(* Logix 5000 project; controller Hardy_1769_Sample_Program vendor 1 type 14 code 151 rev 30.11; software revision 30.02 *)

TASK MainTask (continuous, watchdog 500 ms) : Hardy_HI1769_Scale_0, Hardy_HI1769_Scale_1

MODULES
   Local : vendor 1 type 14 code 151 (Compact 0, rev 30.11)
      Counters : Embedded (Compact 3, rev 1.1, Output RPI 20 ms)
      Hardy_HI1769_2WS : vendor 258 type 100 code 5 (Compact 4, rev 3.1, Output RPI 2 ms)
      Discrete_IO : Embedded (Compact 1, rev 3.1, Output RPI 20 ms)
      Analog_IO : Embedded (Compact 2, rev 1.1, Output RPI 80 ms)
END_MODULES

TYPE HardyC2SerialNumber :   // C2 serial number, sensitivity, and capacity
STRUCT
   serialnumber : INT[8];
   sensitivity : DINT;
   capacity : DINT;
   unused0 : INT;
   unused1 : INT;
END_STRUCT
END_TYPE

TYPE HardyCmdResult :   // Results returned for commands without specific data associated with command.
STRUCT
   Cmd : INT;
   CmdStatus : INT;
END_STRUCT
END_TYPE

TYPE HardyFloatParam0 :   // parameter 0 values using float values.
STRUCT
   ChanActive : INT;
   Metric : INT;
   Waversaver : INT;
   NumAverages : INT;
   ZeroTrackEnable : INT;
   ROC_Time_Base : INT;
   AutoZeroTol : REAL;
   MotionTol : REAL;
   ZeroTol : REAL;
   unused1 : INT;
   unused2 : INT;
END_STRUCT
END_TYPE

TYPE HardyFloatParam1 :   // parameter 1 values with float variables.
STRUCT
   TareWeight : REAL;
   SpanWeight : REAL;
   CalLowWeight : REAL;
   ZeroCount : DINT;
   CalZeroCount : DINT;
   CalLowCount : DINT;
   CalHighCount : DINT;
END_STRUCT
END_TYPE

TYPE HardyFloatSysTest :   // With IT jbox, gives weight readings from individual load cells, internal ref weight and junction box ref weight with floats..
STRUCT
   Cmd : INT;
   NSensors : INT;
   CombinedGross : REAL;
   Gross1 : REAL;
   Gross2 : REAL;
   Gross3 : REAL;
   Gross4 : REAL;
   InternalWgt : REAL;
   JBOXWgt : REAL;
END_STRUCT
END_TYPE

TYPE HardyFloatWeight :   // default return from module when no command given.
STRUCT
   Channel_Status : INT;
   FirmwareRev : INT;
   Gross_Weight : REAL;
   Net_Weight : REAL;
   Metric : INT;
   CalType : INT;
   ADC_Counts : DINT;
   Rate_of_Change : REAL;
   Serial_Number : INT;
   Conv_Count : INT;
END_STRUCT
END_TYPE

TYPE HardyIntParam0 :   // parameter 0 values using integer values.
STRUCT
   ChanActive : INT;
   Metric : INT;
   Waversaver : INT;
   NumAverages : INT;
   ZeroTrackEnable : INT;
   ROC_Time_Base : INT;
   AutoZeroTol : DINT;
   MotionTol : DINT;
   ZeroTol : DINT;
   unused1 : INT;
   unused2 : INT;
END_STRUCT
END_TYPE

TYPE HardyIntParam1 :   // parameter 1 values with integer variables.
STRUCT
   TareWeight : DINT;
   SpanWeight : DINT;
   CalLowWeight : DINT;
   ZeroCount : DINT;
   CalZeroCount : DINT;
   CalLowCount : DINT;
   CalHighCount : DINT;
END_STRUCT
END_TYPE

TYPE HardyIntSysTest :   // With IT jbox, gives weight readings from individual load cells, internal ref weight and junction box ref weight with integer.
STRUCT
   Cmd : INT;
   NSensors : INT;
   CombinedGross : DINT;
   Gross1 : DINT;
   Gross2 : DINT;
   Gross3 : DINT;
   Gross4 : DINT;
   InternalWgt : DINT;
   JBOXWgt : DINT;
END_STRUCT
END_TYPE

TYPE HardyIntWeight :   // default return from module when no command given.
STRUCT
   Channel_Status : INT;
   FirmwareRev : INT;
   Gross_Weight : DINT;
   Net_Weight : DINT;
   Metric : INT;
   CalType : INT;
   ADC_Counts : DINT;
   Rate_of_Change : DINT;
   Serial_Number : INT;
   Conv_Count : INT;
END_STRUCT
END_TYPE

TYPE HardySystemCal :
STRUCT
   cmd : INT;
   status : INT;
   serialnumber : INT;
   Unused : INT;
   Gain : DINT;
   Offset : DINT;
   Zero : DINT;
END_STRUCT
END_TYPE

TYPE HardySysTest2 :   // With IT jbox, gives mV/V of individual load cells, reads sense volts, load cell resistance, and results of return to zero test
STRUCT
   Cmd : INT;
   return_to_zero : INT;
   mvPerVCombined : DINT;
   mvPerV1 : DINT;
   mvPerV2 : DINT;
   mvPerV3 : DINT;
   mvPerV4 : DINT;
   SenseV : DINT;
   InputRes : DINT;
END_STRUCT
END_TYPE

PROGRAM Hardy_HI1769_Scale_0   (* main routine MainRoutine *)
VAR
   ADC_Problem : BOOL := 1;
   Control_Bits : BOOL[32] := ([30] := 1, [31] := 1);   // Control Bits For All Routines In This Program
        [19]   // Start Tare
        [4]   // Do Traditional CAL HIGH
        [11]   // Start Read Parameters 0
        [21]   // Start Write Metric
        [13]   // Start Read Parameters 1
        [23]   // Start Write Non Volatile
        [15]   // Start Read Serial Numbers
        [25]   // Start Write Parameters 0
        [17]   // Start Reload Non Volatile
        [27]   // Starte Write Parameters 1
        [29]   // Start Zero
        [1]   // Start C2 CAL
        [3]   // Start C2 Search
        [5]   // Start CAL High
        [7]   // Start CAL Low
        [9]   // Start Defaults
        [10]   // Do Read Parameters 0
        [20]   // Do Write Metric
        [12]   // Do Read Parameters 1
        [22]   // Do Write Non Volatile
        [14]   // Do Read Serial Numbers
        [24]   // Do Write Parameters 0
        [16]   // Do Reload Non Volatile
        [26]   // Do Write Parameters 1
        [18]   // TARE the Net Weight
        [0]   // Do C2 CAL
        [2]   // Do C2 Search
        [8]   // Set to Defaults
        [6]   // Do Traditional CAL LOW
        [28]   // ZERO the Gross Weight
   Control_Bits1 : BOOL[32];
        [4]   // Start Stability Test
        [3]   // Do Stability Test
        [5]   // Stop Stability Test
        [2]   // Read Test Data
        [1]   // Start IT Test
        [0]   // Do IT Test
   Current_Metric : INT := 1;   // Current Metric Settings
   Default_Return_Float : HardyFloatWeight := (Channel_Status := 16#8040, Gross_Weight := -128.37949, Net_Weight := -128.37949, Metric := 16#0040, ADC_Counts := 1429576, Rate_of_Change := 514.0, Conv_Count := 32546);   // Default Return Values With Weight In Foating Point Format
   Default_Return_Int : HardyIntWeight := (Channel_Status := 16#8001, FirmwareRev := 16#0303, Gross_Weight := 3143, Net_Weight := 2015, Metric := 16#0001, CalType := 1, ADC_Counts := 8388606, Serial_Number := 4260, Conv_Count := -24233);   // Default Return Values With Weight In Integer Format
   Error_Flag : BOOL;
   Hardy_HI1769WS_Ch0_Channel_Command_Echo : INT;   // Ch0 Current Command Echo 16#0000 No Command 16#0001 Zero Command 16#0002 Tare Command 16#0003 Write Metric 16#0004 Write Non-Volatile 16#0010 Reload Non-Volatile 16#0064 Cal Low 16#0065 Cal High 16#0066 C2 Cal 16#0067 Write Param 0 16#0068 Write Param 1 16#0069 Read Param 0 16#006A Read Param 1 16#006B Stability Test 16#006C IT Test Results 16#006D Do IT Test 16#006E Search C2 16#006F IT Weigh Result 16#0070 C2 Serial 16#0094 Set Defaults 16#00FF Sofware Version
   Hardy_HI1769WS_Ch0_Channel_Last_Command : INT := 16#0069;   // Ch0 Last Command Sent 16#0000 No Command 16#0001 Zero Command 16#0002 Tare Command 16#0003 Write Metric 16#0004 Write Non-Volatile 16#0010 Reload Non-Volatile 16#0064 Cal Low 16#0065 Cal High 16#0066 C2 Cal 16#0067 Write Param 0 16#0068 Write Param 1 16#0069 Read Param 0 16#006A Read Param 1 16#006B Stability Test 16#006C IT Test Results 16#006D Do IT Test 16#006E Search C2 16#006F IT Weigh Result 16#0070 C2 Serial 16#0094 Set Defaults 16#00FF Sofware Version
   Hardy_HI1769WS_Ch0_Channel_Status : INT := 16#8001;   // Ch0 Channel Status 16#0001 ADC Error 16#0002 AD Failure 16#0040 Motion 16#0080 Not Calibrated 16#0100 Eeprom Write 16#0200 Default Command Sent 16#8000 Ch Enabled
   Hardy_HI1769WS_Ch0_Command_Status : INT;   // Ch0 Current Command Status 0 Success 1 ADC Error 2 ADC Failure 40 In Motion -3 Out of Tolerance -4 Out of Range -5 No Such Command -6 No C2 Device -7 C2 Unequal Caps -8 Hard Cal Not Enough Counts
   Hardy_HI1769WS_Ch0_Gross_Display_Float : REAL;   // Ch0 Gross Weight Float
   Hardy_HI1769WS_Ch0_Gross_Display_Int : DINT := 3143;   // Ch0 Gross Weight Int
   Hardy_HI1769WS_Ch0_Last_Command_Status : INT;   // Ch0 Last Command Status 0 Success 1 ADC Error 2 ADC Failure 40 In Motion -3 Out of Tolerance -4 Out of Range -5 No Such Command -6 No C2 Device -7 C2 Unequal Caps -8 Hard Cal Not Enough Counts
   Hardy_HiI1769WS_Ch0_Net_Display_Float : REAL;   // Ch0 Net Weight Float
   Hardy_HiI1769WS_Ch0_Net_Display_Int : DINT := 2015;   // Ch0 Net Weight Int
   HI1769WS_Ch0_One_Decimal_Place_Float : REAL := 314.3;   // One Decimal Place
   HI1769WS_Ch0_One_Decimal_Place_Int : DINT := 56250;
   HI1769WS_Ch0_Two_Decimal_Places_Float : REAL := 5.64;   // Two Decimals
   HI1769WS_Ch0_Two_Decimal_Places_Int : DINT := 56;
   IT_Float_Test : HardyFloatSysTest := (Cmd := 16#006d, NSensors := 4, CombinedGross := 24.86434, Gross1 := 5.319677, Gross2 := 5.8995957, Gross3 := 6.7579713, Gross4 := 6.8011603, InternalWgt := 822.809, JBOXWgt := 376.3745);   // IT Test Results In Float Format
   IT_Int_Test : HardyIntSysTest;   // IT Test Results In Int Format
   Metric : INT := 64;   // New Metric Setting
   Motion : BOOL;
   mV_Test_Results : HardySysTest2 := (Cmd := 16#006c, return_to_zero := 2#0000_0000_0001_1001, mvPerVCombined := 2053, mvPerV1 := 2332, mvPerV2 := 1887, mvPerV3 := 2135, mvPerV4 := 1816, SenseV := 46581, InputRes := 76);   // Results Second Part IT Test
   Number_Of_Sensors : INT := 4;   // Number Of Sensors on System, Used For IT System Test
   One_Shot : BOOL[32];   // One Shots For Program Control
        [16]   // One Shot to Clear Tags
        [18]   // ONE SHOT TO CLEAR TAGS
        [15]   // One Shot to Clear Tags
        [11]   // One Shot to Clear Tags
        [9]   // One Shot to Clear Tags
        [13]   // ONE SHOT TO CLEAR TAGS
        [10]   // One Shot to Clear Tags
        [19]   // ONE SHOT TO CLEAR TAGS
        [7]   // One Shot to Clear Tags
        [3]   // One Shot to Clear Tags
        [12]   // One Shot to Clear Tags
        [5]   // One Shot to Clear Tags
        [1]   // ONE SHOT TO CLEAR TAGS
        [17]   // ONE SHOT TO CLEAR TAGS
        [14]   // One Shot to Clear Tags
        [0]   // One Shot To Clear Tags
        [2]   // One Shot to Clear Tags
        [4]   // One Shot to Clear Tags
        [6]   // One Shot to Clear Tags
        [8]   // One Shot to Clear Tags
   Read_Float_Parameters_0 : HardyFloatParam0 := (ChanActive := 1, Metric := 16#0040, Waversaver := 2, NumAverages := 10, AutoZeroTol := 10.0, MotionTol := 3.0, ZeroTol := 3.0);   // Read Parameter 0 Values From Module Using Float Values
   Read_Float_Parameters_1 : HardyFloatParam1 := (SpanWeight := 5.0, ZeroCount := 1202223, CalZeroCount := 1202223, CalLowCount := 1202223, CalHighCount := 1191147);   // Read Parameter 1 Values From Module Using Float Values
   Read_Int_Parameters_0 : HardyIntParam0 := (ChanActive := 1, Metric := 16#0001, Waversaver := 3, NumAverages := 20, ROC_Time_Base := 10, AutoZeroTol := 10, MotionTol := 5, ZeroTol := 10);   // Read Parameter 0 Values From Module Using Int Values
   Read_Int_Parameters_1 : HardyIntParam1 := (SpanWeight := 600, CalLowWeight := 200, ZeroCount := 2399782, CalZeroCount := 2033102, CalLowCount := 2155320, CalHighCount := 2399757);   // Read Parameter 1 Values From Module Using Int Values
   Sensor_Select : INT := 1;   // Load Cell Selected For Reading Serial Number
   Serial_Number : HardyC2SerialNumber := (serialnumber[0] := '$00 ', serialnumber[1] := '$00 ', serialnumber[2] := '$001', serialnumber[3] := '$006', serialnumber[4] := '$004', serialnumber[5] := '$001', serialnumber[6] := '$009', serialnumber[7] := '$005', sensitivity := 30267, capacity := 150);   // Serial Number of Selected Load Cell Analog With Sensitivity and Capacity
   Signal_Select : INT := 1;   // Signal To Select For Stability Test
   Stability_Float : HardyFloatWeight := (Channel_Status := 16#8000, Gross_Weight := -1.7534312, Net_Weight := -1.7534312, Metric := 16#0040, ADC_Counts := 1125882, Rate_of_Change := 257.0, Conv_Count := 17903);   // Results Of Stability Test Float Format
   Stability_Int : HardyIntWeight;   // Results Of Stability Test Int Format
   Status_Return : HardyCmdResult := (Cmd := 16#0069);   // Command Status Returned
   Write_Float_Param_0 : HardyFloatParam0 := (ChanActive := 1, Metric := 16#0040, Waversaver := 2, NumAverages := 10, AutoZeroTol := 10.0, MotionTol := 3.0, ZeroTol := 3.0);   // New Parameter 0 Values In Float Format
   Write_Float_Param_1 : HardyFloatParam1 := (SpanWeight := 4.0);   // New Parameter 1 Values In Float Format
   Write_Int_Param_0 : HardyIntParam0 := (ChanActive := 1, Waversaver := 2, NumAverages := 20, AutoZeroTol := 10, MotionTol := 5, ZeroTol := 10);   // New Parameter 0 Value Int Format
   Write_Int_Param_1 : HardyIntParam1 := (TareWeight := 25, SpanWeight := 1000);   // New Parameter 1 Value Int Format
END_VAR

ROUTINE C2_Cal   (* ladder *)
// Do C2 Calibration
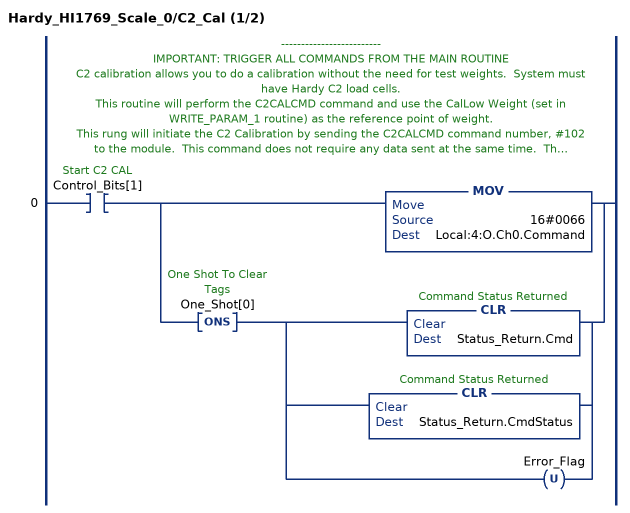
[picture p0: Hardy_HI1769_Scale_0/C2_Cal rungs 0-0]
   // -------------------------
   // IMPORTANT: TRIGGER ALL COMMANDS FROM THE MAIN ROUTINE
   // C2 calibration allows you to do a calibration without the need for test weights.  System must have Hardy C2 load cells.
   // This routine will perform the C2CALCMD command and use the CalLow Weight (set in WRITE_PARAM_1 routine) as the reference point of weight.
   // This rung will initiate the C2 Calibration by sending the C2CALCMD command number, #102 to the module.  This command does not require any data sent at the same time.  The command number will be placed into the first word (Local:1:O.Ch0.Command) of the output table.
   // Here the program will also clear the Status_Return tag and ERROR_FLAG of any previous values before running this command and receiving its return values.
   // IMPORTANT: TRIGGER ALL COMMANDS FROM THE MAIN ROUTINE
   // ------------------------------------------------------------------------------------------------------------------
   0: XIC(Control_Bits[1])[MOV(16#0066,Local:4:O.Ch0.Command) ,ONS(One_Shot[0]) [CLR(Status_Return.Cmd) ,CLR(Status_Return.CmdStatus) ,OTU(Error_Flag) ] ];
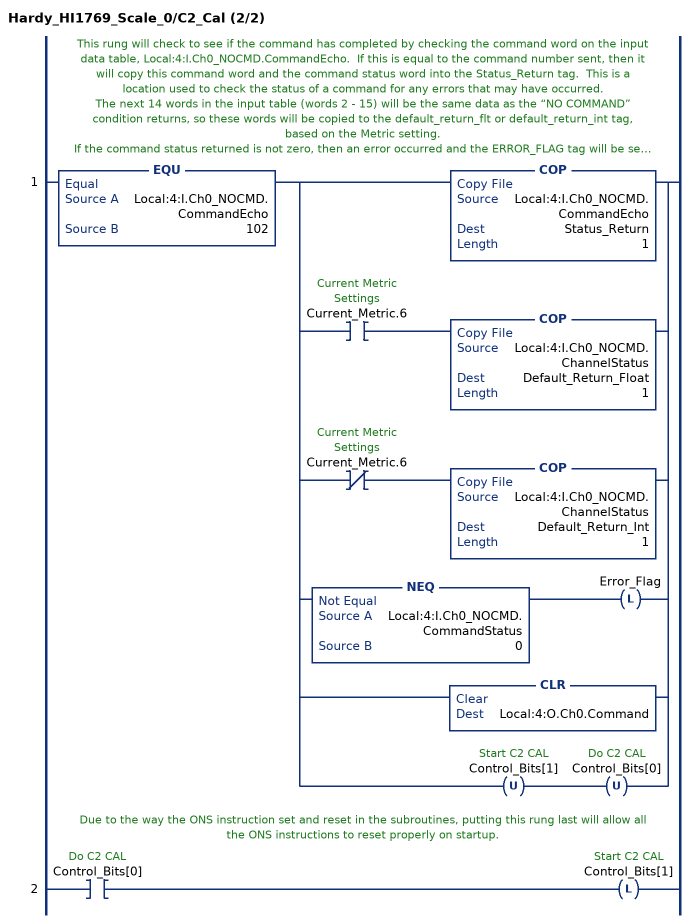
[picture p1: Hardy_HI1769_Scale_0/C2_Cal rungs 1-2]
   // This rung will check to see if the command has completed by checking the command word on the input data table, Local:4:I.Ch0_NOCMD.CommandEcho.  If this is equal to the command number sent, then it will copy this command word and the command status word into the Status_Return tag.  This is a location used to check the status of a command for any errors that may have occurred.
   // The next 14 words in the input table (words 2 - 15) will be the same data as the “NO COMMAND” condition returns, so these words will be copied to the default_return_flt or default_return_int tag, based on the Metric setting.
   // If the command status returned is not zero, then an error occurred and the ERROR_FLAG tag will be set high.  The user can monitor this bit to know if an error occurred and then check the Status_Return tag for the command and status return.
   // Finally, the command is cleared from the output table,Local:4:O.Ch0.Command, and any control bits are cleared.
   1: EQU(Local:4:I.Ch0_NOCMD.CommandEcho,102)[COP(Local:4:I.Ch0_NOCMD.CommandEcho,Status_Return,1) ,XIC(Current_Metric.6) COP(Local:4:I.Ch0_NOCMD.ChannelStatus,Default_Return_Float,1) ,XIO(Current_Metric.6) COP(Local:4:I.Ch0_NOCMD.ChannelStatus,Default_Return_Int,1) ,NEQ(Local:4:I.Ch0_NOCMD.CommandStatus,0) OTL(Error_Flag) ,CLR(Local:4:O.Ch0.Command) ,OTU(Control_Bits[1]) OTU(Control_Bits[0]) ];
   // Due to the way the ONS instruction set and reset in the subroutines, putting this rung last will allow all the ONS instructions to reset properly on startup.
   2: XIC(Control_Bits[0])OTL(Control_Bits[1]);
END_ROUTINE

ROUTINE C2_Search   (* ladder *)
// Check for Number of C2 Load Cells on System
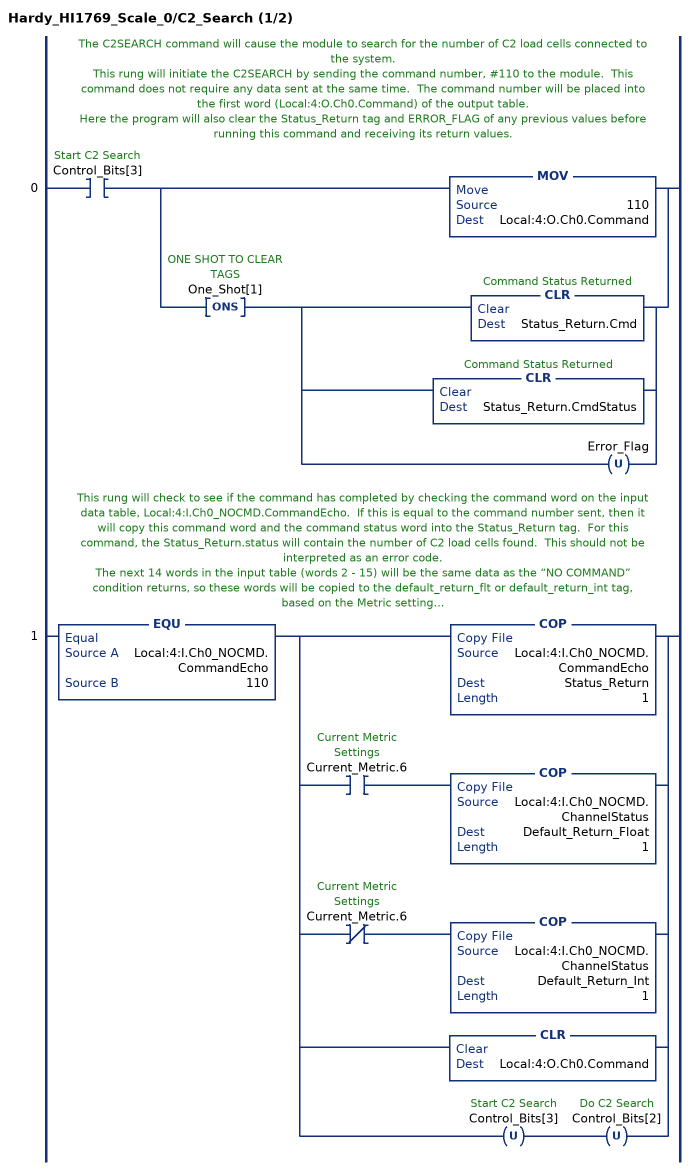
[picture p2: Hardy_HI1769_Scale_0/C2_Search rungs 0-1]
   // The C2SEARCH command will cause the module to search for the number of C2 load cells connected to the system.
   // This rung will initiate the C2SEARCH by sending the command number, #110 to the module.  This command does not require any data sent at the same time.  The command number will be placed into the first word (Local:4:O.Ch0.Command) of the output table.
   // Here the program will also clear the Status_Return tag and ERROR_FLAG of any previous values before running this command and receiving its return values.
   0: XIC(Control_Bits[3])[MOV(110,Local:4:O.Ch0.Command) ,ONS(One_Shot[1]) [CLR(Status_Return.Cmd) ,CLR(Status_Return.CmdStatus) ,OTU(Error_Flag) ] ];
   // This rung will check to see if the command has completed by checking the command word on the input data table, Local:4:I.Ch0_NOCMD.CommandEcho.  If this is equal to the command number sent, then it will copy this command word and the command status word into the Status_Return tag.  For this command, the Status_Return.status will contain the number of C2 load cells found.  This should not be interpreted as an error code.
   // The next 14 words in the input table (words 2 - 15) will be the same data as the “NO COMMAND” condition returns, so these words will be copied to the default_return_flt or default_return_int tag, based on the Metric setting.
   // Finally, the command is cleared from the output table, Local:4:O.Ch0.Command, and any control bits are cleared.
   1: EQU(Local:4:I.Ch0_NOCMD.CommandEcho,110)[COP(Local:4:I.Ch0_NOCMD.CommandEcho,Status_Return,1) ,XIC(Current_Metric.6) COP(Local:4:I.Ch0_NOCMD.ChannelStatus,Default_Return_Float,1) ,XIO(Current_Metric.6) COP(Local:4:I.Ch0_NOCMD.ChannelStatus,Default_Return_Int,1) ,CLR(Local:4:O.Ch0.Command) ,OTU(Control_Bits[3]) OTU(Control_Bits[2]) ];
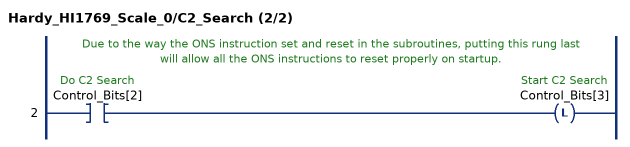
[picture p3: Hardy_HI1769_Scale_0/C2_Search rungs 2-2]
   // Due to the way the ONS instruction set and reset in the subroutines, putting this rung last will allow all the ONS instructions to reset properly on startup.
   2: XIC(Control_Bits[2])OTL(Control_Bits[3]);
END_ROUTINE

ROUTINE Cal_High   (* ladder *)
// Do High Point of Hard Calibration
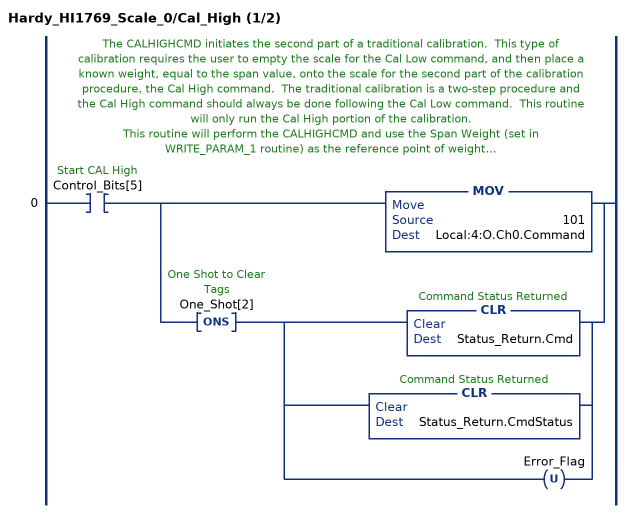
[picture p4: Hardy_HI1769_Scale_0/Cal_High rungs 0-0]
   // The CALHIGHCMD initiates the second part of a traditional calibration.  This type of calibration requires the user to empty the scale for the Cal Low command, and then place a known weight, equal to the span value, onto the scale for the second part of the calibration procedure, the Cal High command.  The traditional calibration is a two-step procedure and the Cal High command should always be done following the Cal Low command.  This routine will only run the Cal High portion of the calibration.
   // This routine will perform the CALHIGHCMD and use the Span Weight (set in WRITE_PARAM_1 routine) as the reference point of weight.
   // NOTE:  User must have the weight on the scale prior to initiating this command.
   // This rung will initiate the Cal High by sending the Cal High command number, #101 to the module.  This command does not require any data sent at the same time.  The command number will be placed into the first word (Local:4:O.Ch0.Command) of the output table.
   // Here the program will also clear the Status_Return tag and ERROR_FLAG of any previous values before running this command and receiving its return values.
   0: XIC(Control_Bits[5])[MOV(101,Local:4:O.Ch0.Command) ,ONS(One_Shot[2]) [CLR(Status_Return.Cmd) ,CLR(Status_Return.CmdStatus) ,OTU(Error_Flag) ] ];
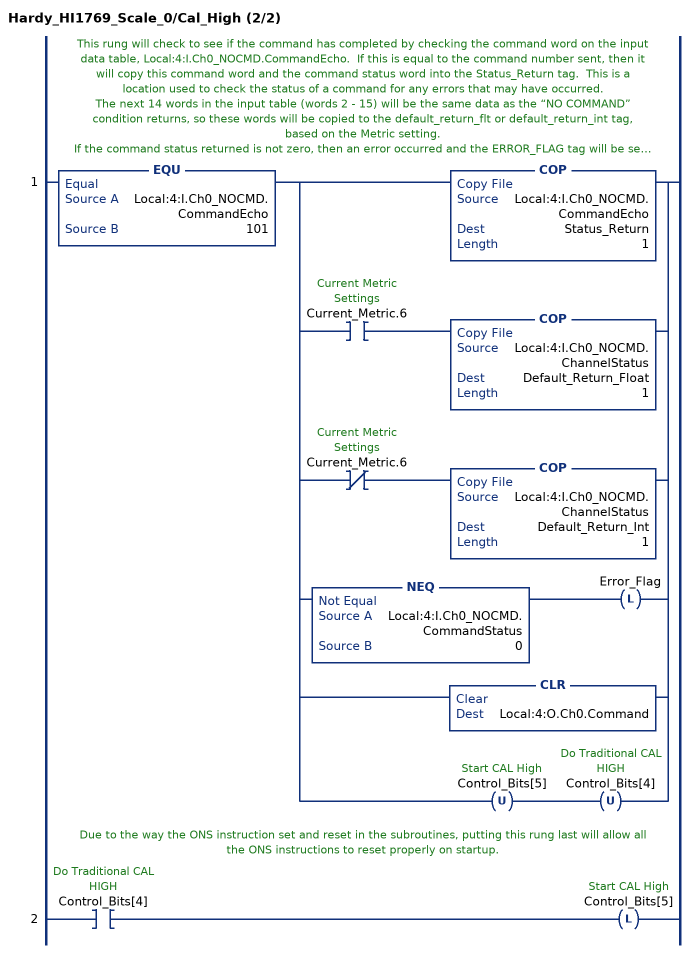
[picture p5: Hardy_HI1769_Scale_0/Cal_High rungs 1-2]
   // This rung will check to see if the command has completed by checking the command word on the input data table, Local:4:I.Ch0_NOCMD.CommandEcho.  If this is equal to the command number sent, then it will copy this command word and the command status word into the Status_Return tag.  This is a location used to check the status of a command for any errors that may have occurred.
   // The next 14 words in the input table (words 2 - 15) will be the same data as the “NO COMMAND” condition returns, so these words will be copied to the default_return_flt or default_return_int tag, based on the Metric setting.
   // If the command status returned is not zero, then an error occurred and the ERROR_FLAG tag will be set high.  The user can monitor this bit to know if an error occurred and then check the Status_Return tag for the command and status return.
   // Finally, the command is cleared from the output table,Local:1:O.Ch0.Command, and any control bits are cleared.
   1: EQU(Local:4:I.Ch0_NOCMD.CommandEcho,101)[COP(Local:4:I.Ch0_NOCMD.CommandEcho,Status_Return,1) ,XIC(Current_Metric.6) COP(Local:4:I.Ch0_NOCMD.ChannelStatus,Default_Return_Float,1) ,XIO(Current_Metric.6) COP(Local:4:I.Ch0_NOCMD.ChannelStatus,Default_Return_Int,1) ,NEQ(Local:4:I.Ch0_NOCMD.CommandStatus,0) OTL(Error_Flag) ,CLR(Local:4:O.Ch0.Command) ,OTU(Control_Bits[5]) OTU(Control_Bits[4]) ];
   // Due to the way the ONS instruction set and reset in the subroutines, putting this rung last will allow all the ONS instructions to reset properly on startup.
   2: XIC(Control_Bits[4])OTL(Control_Bits[5]);
END_ROUTINE

ROUTINE Cal_Low   (* ladder *)
// Do Low Point of Hard Calibration
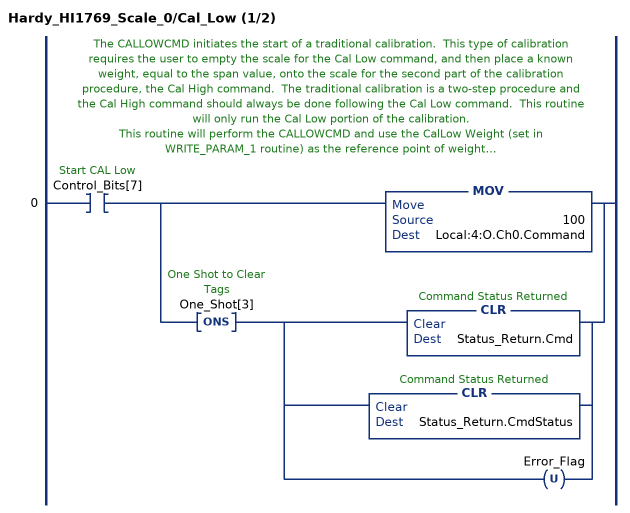
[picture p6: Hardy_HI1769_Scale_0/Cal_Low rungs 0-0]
   // The CALLOWCMD initiates the start of a traditional calibration.  This type of calibration requires the user to empty the scale for the Cal Low command, and then place a known weight, equal to the span value, onto the scale for the second part of the calibration procedure, the Cal High command.  The traditional calibration is a two-step procedure and the Cal High command should always be done following the Cal Low command.  This routine will only run the Cal Low portion of the calibration.
   // This routine will perform the CALLOWCMD and use the CalLow Weight (set in WRITE_PARAM_1 routine) as the reference point of weight.
   // This rung will initiate the Cal Low by sending the Cal Low command number, #100 to the module.  This command does not require any data sent at the same time.  The command number will be placed into the first word Local:4:O.Ch0.Command) of the output table.
   // Here the program will also clear the Status_Return tag and ERROR_FLAG of any previous values before running this command and receiving its return values.
   0: XIC(Control_Bits[7])[MOV(100,Local:4:O.Ch0.Command) ,ONS(One_Shot[3]) [CLR(Status_Return.Cmd) ,CLR(Status_Return.CmdStatus) ,OTU(Error_Flag) ] ];
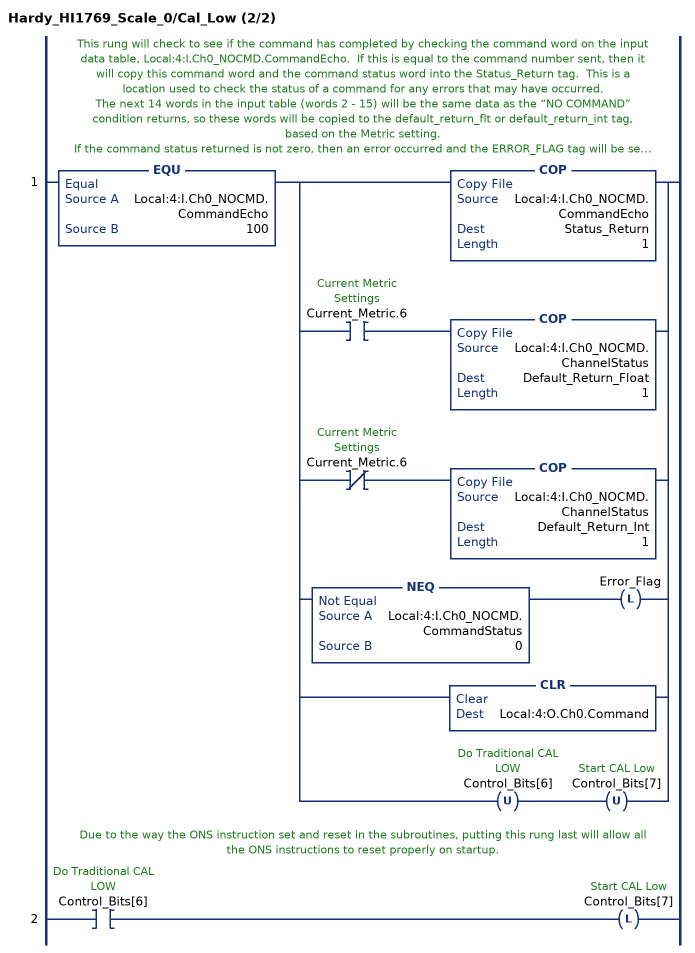
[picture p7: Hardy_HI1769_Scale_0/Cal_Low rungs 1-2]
   // This rung will check to see if the command has completed by checking the command word on the input data table, Local:4:I.Ch0_NOCMD.CommandEcho.  If this is equal to the command number sent, then it will copy this command word and the command status word into the Status_Return tag.  This is a location used to check the status of a command for any errors that may have occurred.
   // The next 14 words in the input table (words 2 - 15) will be the same data as the “NO COMMAND” condition returns, so these words will be copied to the default_return_flt or default_return_int tag, based on the Metric setting.
   // If the command status returned is not zero, then an error occurred and the ERROR_FLAG tag will be set high.  The user can monitor this bit to know if an error occurred and then check the Status_Return tag for the command and status return.
   // Finally, the command is cleared from the output table, Local:4:O.Ch0.Command, and any control bits are cleared.
   1: EQU(Local:4:I.Ch0_NOCMD.CommandEcho,100)[COP(Local:4:I.Ch0_NOCMD.CommandEcho,Status_Return,1) ,XIC(Current_Metric.6) COP(Local:4:I.Ch0_NOCMD.ChannelStatus,Default_Return_Float,1) ,XIO(Current_Metric.6) COP(Local:4:I.Ch0_NOCMD.ChannelStatus,Default_Return_Int,1) ,NEQ(Local:4:I.Ch0_NOCMD.CommandStatus,0) OTL(Error_Flag) ,CLR(Local:4:O.Ch0.Command) ,OTU(Control_Bits[6]) OTU(Control_Bits[7]) ];
   // Due to the way the ONS instruction set and reset in the subroutines, putting this rung last will allow all the ONS instructions to reset properly on startup.
   2: XIC(Control_Bits[6])OTL(Control_Bits[7]);
END_ROUTINE

ROUTINE Defaults   (* ladder *)
// Sets Module Back to Default Settings
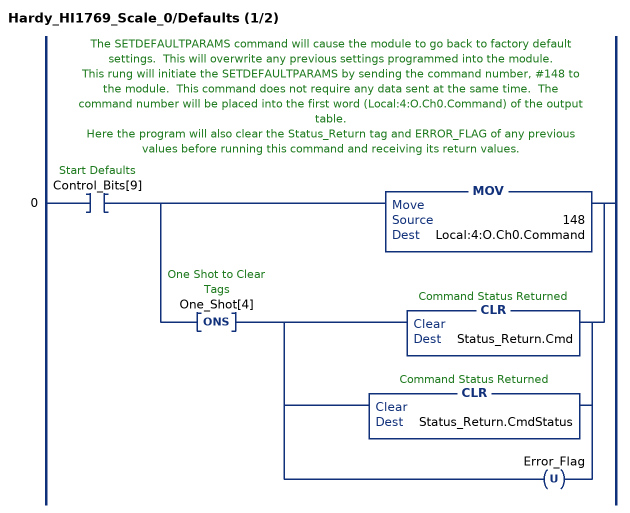
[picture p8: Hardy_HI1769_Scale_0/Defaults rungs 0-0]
   // The SETDEFAULTPARAMS command will cause the module to go back to factory default settings.  This will overwrite any previous settings programmed into the module.
   // This rung will initiate the SETDEFAULTPARAMS by sending the command number, #148 to the module.  This command does not require any data sent at the same time.  The command number will be placed into the first word (Local:4:O.Ch0.Command) of the output table.
   // Here the program will also clear the Status_Return tag and ERROR_FLAG of any previous values before running this command and receiving its return values.
   0: XIC(Control_Bits[9])[MOV(148,Local:4:O.Ch0.Command) ,ONS(One_Shot[4]) [CLR(Status_Return.Cmd) ,CLR(Status_Return.CmdStatus) ,OTU(Error_Flag) ] ];
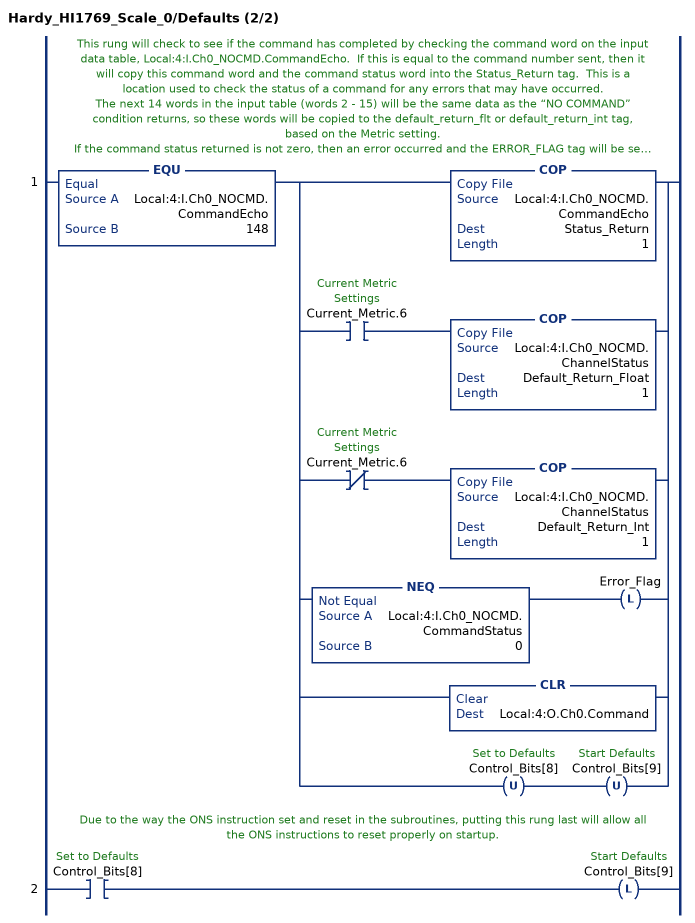
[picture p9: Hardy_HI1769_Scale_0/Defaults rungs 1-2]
   // This rung will check to see if the command has completed by checking the command word on the input data table, Local:4:I.Ch0_NOCMD.CommandEcho.  If this is equal to the command number sent, then it will copy this command word and the command status word into the Status_Return tag.  This is a location used to check the status of a command for any errors that may have occurred.
   // The next 14 words in the input table (words 2 - 15) will be the same data as the “NO COMMAND” condition returns, so these words will be copied to the default_return_flt or default_return_int tag, based on the Metric setting.
   // If the command status returned is not zero, then an error occurred and the ERROR_FLAG tag will be set high.  The user can monitor this bit to know if an error occurred and then check the Status_Return tag for the command and status return.
   // Finally, the command is cleared from the output table, Local:4:O.Ch0.Command, and any control bits are cleared.
   1: EQU(Local:4:I.Ch0_NOCMD.CommandEcho,148)[COP(Local:4:I.Ch0_NOCMD.CommandEcho,Status_Return,1) ,XIC(Current_Metric.6) COP(Local:4:I.Ch0_NOCMD.ChannelStatus,Default_Return_Float,1) ,XIO(Current_Metric.6) COP(Local:4:I.Ch0_NOCMD.ChannelStatus,Default_Return_Int,1) ,NEQ(Local:4:I.Ch0_NOCMD.CommandStatus,0) OTL(Error_Flag) ,CLR(Local:4:O.Ch0.Command) ,OTU(Control_Bits[8]) OTU(Control_Bits[9]) ];
   // Due to the way the ONS instruction set and reset in the subroutines, putting this rung last will allow all the ONS instructions to reset properly on startup.
   2: XIC(Control_Bits[8])OTL(Control_Bits[9]);
END_ROUTINE

ROUTINE IT_Test   (* ladder *)
// Runs IT Scale Test
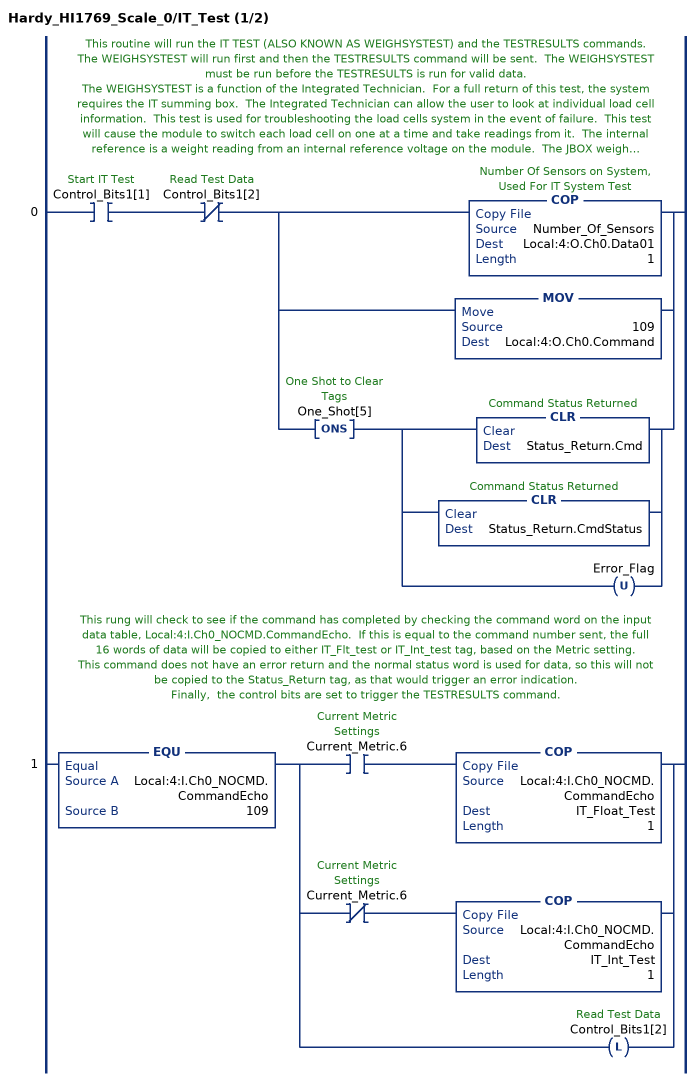
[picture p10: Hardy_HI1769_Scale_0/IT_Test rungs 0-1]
   // This routine will run the IT TEST (ALSO KNOWN AS WEIGHSYSTEST) and the TESTRESULTS commands.  The WEIGHSYSTEST will run first and then the TESTRESULTS command will be sent.  The WEIGHSYSTEST must be run before the TESTRESULTS is run for valid data.
   // The WEIGHSYSTEST is a function of the Integrated Technician.  For a full return of this test, the system requires the IT summing box.  The Integrated Technician can allow the user to look at individual load cell information.  This test is used for troubleshooting the load cells system in the event of failure.  This test will cause the module to switch each load cell on one at a time and take readings from it.  The internal reference is a weight reading from an internal reference voltage on the module.  The JBOX weight reading is from a reference voltage on the JBOX.
   // When the system is equipped with the IT summing box, this test will return the following information to:
   // **Local Tags IT_Float_Test or Local Tags IT_Int depending on Metrix bit 6**
   // Word 0 = Command Number - 109
   // Word 1 = Number of sensors - as entered in the command
   // Word 2 = Combined gross weight LSW - Gross weight from all load cells
   // Word 3 = Combined gross weight MSW - Gross weight from all load cells
   // Word 4 = Gross weight load cell number 1 LSW - Individual weight from load cell #1
   // Word 5 = Gross weight load cell number 1 MSW - Individual weight from load cell #1
   // Word 6 = Gross weight load cell number 2 LSW - Individual weight from load cell #2
   // Word 7 = Gross weight load cell number 2 MSW - Individual weight from load cell #2
   // Word 8 = Gross weight load cell number 3 LSW - Individual weight from load cell #3
   // Word 9 = Gross weight load cell number 3 MSW - Individual weight from load cell #3
   // Word 10 = Gross weight load cell number 4 LSW - Individual weight from load cell #4
   // Word 11 = Gross weight load cell number 4 MSW - Individual weight from load cell #4
   // Word 12 = Internal reference LSW - Weight reading from internal reference voltage
   // Word 13 = Internal reference MSW - Weight reading from internal reference voltage
   // Word 14 = Jbox reference weight LSW - Weight reading from JBOX reference voltage
   // Word 15 = Jbox reference weight MSW - Weight reading from JBOX reference voltage
   // Words 2-15 are weight values, scaled according to the current Metric parameter value.
   // NOTES:
   // **The word locations in the input table will have the names as used for the default return, and those names will not apply to the return values for this command. So the copy
   // command in the next rung will copy the data into a UDT with the proper names for the data.  Users should reference these UDTs for the data instead of the input tables.**
   // **If system has fewer than four load cells, then only the readings from those load cells will be valid, and unused load cell positions should be ignored.**
   // **If the system does not have the IT summing box, then the only valid returns will be the internal reference and the combined readings.**
   // This rung will initiate the IT test by sending the command number, 109, and the number of load cells, from Number_of_Sensors tag, into the output table at Local:4:O.Ch0.Command and Local:1:O.Ch0.Data01.
   // Here the program will also clear the Status_Return tag and ERROR_FLAG of any previous values before running this command and receiving its return values.
   0: XIC(Control_Bits1[1])XIO(Control_Bits1[2])[COP(Number_Of_Sensors,Local:4:O.Ch0.Data01,1) ,MOV(109,Local:4:O.Ch0.Command) ,ONS(One_Shot[5]) [CLR(Status_Return.Cmd) ,CLR(Status_Return.CmdStatus) ,OTU(Error_Flag) ] ];
   // This rung will check to see if the command has completed by checking the command word on the input data table, Local:4:I.Ch0_NOCMD.CommandEcho.  If this is equal to the command number sent, the full 16 words of data will be copied to either IT_Flt_test or IT_Int_test tag, based on the Metric setting.
   // This command does not have an error return and the normal status word is used for data, so this will not be copied to the Status_Return tag, as that would trigger an error indication.
   // Finally,  the control bits are set to trigger the TESTRESULTS command.
   1: EQU(Local:4:I.Ch0_NOCMD.CommandEcho,109)[XIC(Current_Metric.6) COP(Local:4:I.Ch0_NOCMD.CommandEcho,IT_Float_Test,1) ,XIO(Current_Metric.6) COP(Local:4:I.Ch0_NOCMD.CommandEcho,IT_Int_Test,1) ,OTL(Control_Bits1[2]) ];
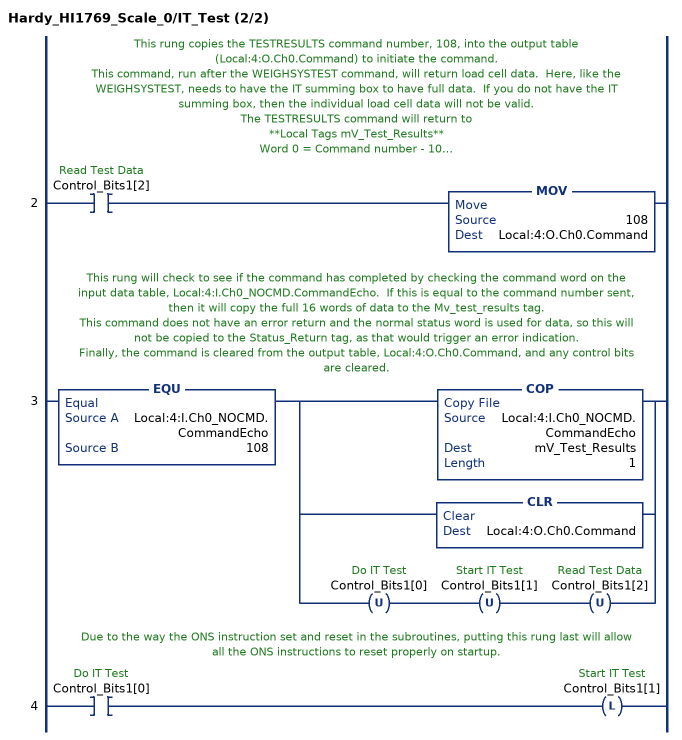
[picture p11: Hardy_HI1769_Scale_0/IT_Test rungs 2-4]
   // This rung copies the TESTRESULTS command number, 108, into the output table (Local:4:O.Ch0.Command) to initiate the command.
   // This command, run after the WEIGHSYSTEST command, will return load cell data.  Here, like the WEIGHSYSTEST, needs to have the IT summing box to have full data.  If you do not have the IT summing box, then the individual load cell data will not be valid.
   // The TESTRESULTS command will return to
   // **Local Tags mV_Test_Results**
   // Word 0 = Command number - 108
   // Word 1 = Return to Zero test. Return to Zero test results are bit coded.  Bits set to 1 indicate Non-Return to Zero.
   //      Bit 0 = Combined Weight
   //      Bit 1 = Load Cell #1 (IT JBOX only)
   //      Bit 2 = Load Cell #2 (IT JBOX only)
   //      Bit 3 = Load Cell #3 (IT JBOX only)
   //      Bit 4 = Load Cell #4 (IT JBOX only)
   // Word 2 = Mv/V Combined LSW - Millivolts/Volt return from all Load Cells combined.
   // Word 3 = Mv/VCombined MSW - Millivolts/Volt return from all Load Cells combined.
   // Word 4 = Mv/V Load Cell #1 LSW - Millivolts/Volt return from Load Cell #1
   // Word 5 = Mv/V Load Cell #1 MSW - Millivolts/Volt return from Load Cell #1
   // Word 6 = Mv/V load cell #2 LSW - Millivolts/Volt return from Load Cell #2
   // Word 7 = Mv/V Load Cell #2 MSW - Millivolts/Volt return from Load Cell #2
   // Word 8 = Mv/V Load Cell #3 LSW - Millivolts/Volt return from Load Cell #3
   // Word 9 = Mv/V Load Cell #3 MSW - Millivolts/Volt return from Load Cell #3
   // Word 10 = Mv/V Load Cell #4 LSW - Millivolts/Volt return from Load Cell #4
   // Word 11 = Mv/V Load Cell #4 MSW - Millivolts/Volt return from Load Cell #4
   // Word 12 = Sense Volts, LSW - Voltage on the Sense Lines
   // Word 13 = Sense Volts, MSW - Voltage on the Sense Lines
   // Word 14 = Resistance LSW - Load Cell input resistance determined from C2 at last calibration
   // Word 15 = Resistance MSW - Load Cell input resistance determined from C2 at last calibration
   // Note:
   // **Words 2-15 are all INTEGER values.  Millivolt/volt readings have 4 decimal places.**
   // **Load cell resistance has zero decimal places.  Sense volts has 2 decimal placed.**
   2: XIC(Control_Bits1[2])MOV(108,Local:4:O.Ch0.Command);
   // This rung will check to see if the command has completed by checking the command word on the input data table, Local:4:I.Ch0_NOCMD.CommandEcho.  If this is equal to the command number sent, then it will copy the full 16 words of data to the Mv_test_results tag.
   // This command does not have an error return and the normal status word is used for data, so this will not be copied to the Status_Return tag, as that would trigger an error indication.
   // Finally, the command is cleared from the output table, Local:4:O.Ch0.Command, and any control bits are cleared.
   3: EQU(Local:4:I.Ch0_NOCMD.CommandEcho,108)[COP(Local:4:I.Ch0_NOCMD.CommandEcho,mV_Test_Results,1) ,CLR(Local:4:O.Ch0.Command) ,OTU(Control_Bits1[0]) OTU(Control_Bits1[1]) OTU(Control_Bits1[2]) ];
   // Due to the way the ONS instruction set and reset in the subroutines, putting this rung last will allow all the ONS instructions to reset properly on startup.
   4: XIC(Control_Bits1[0])OTL(Control_Bits1[1]);
END_ROUTINE

ROUTINE MainRoutine   (* ladder *)
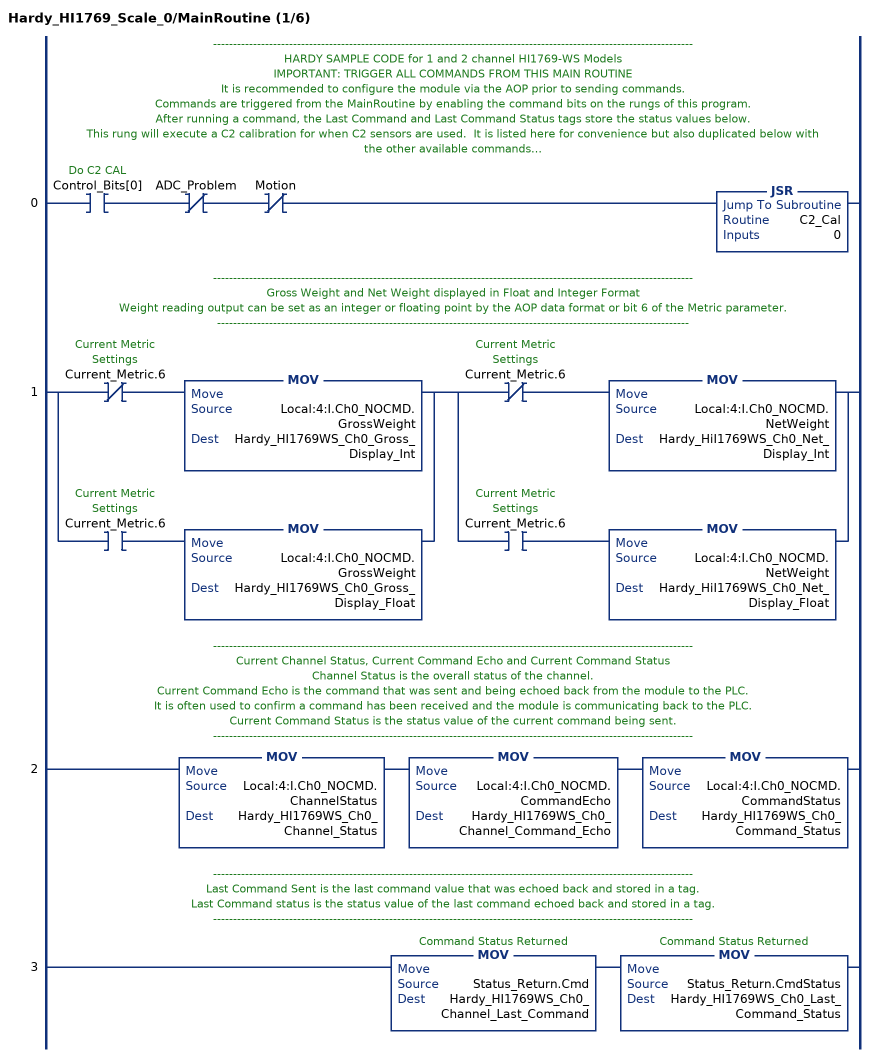
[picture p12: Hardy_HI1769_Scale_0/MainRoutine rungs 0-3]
   // ------------------------------------------------------------------------------------------------------------------------
   // HARDY SAMPLE CODE for 1 and 2 channel HI1769-WS Models
   // IMPORTANT: TRIGGER ALL COMMANDS FROM THIS MAIN ROUTINE
   // It is recommended to configure the module via the AOP prior to sending commands.
   // Commands are triggered from the MainRoutine by enabling the command bits on the rungs of this program.
   // After running a command, the Last Command and Last Command Status tags store the status values below.
   // This rung will execute a C2 calibration for when C2 sensors are used.  It is listed here for convenience but also duplicated below with the other available commands.
   // This rung is conditioned with the ADC problem (often a wiring issue or a damaged cell) and Motion bit.  If either of these conditions is present, the command fails and returns a Command Status.
   // IMPORTANT: TRIGGER ALL COMMANDS FROM THIS MAIN ROUTINE
   // ------------------------------------------------------------------------------------------------------------------------
   0: XIC(Control_Bits[0])XIO(ADC_Problem)XIO(Motion)JSR(C2_Cal,0);
   // ------------------------------------------------------------------------------------------------------------------------
   // Gross Weight and Net Weight displayed in Float and Integer Format
   // Weight reading output can be set as an integer or floating point by the AOP data format or bit 6 of the Metric parameter.
   // ----------------------------------------------------------------------------------------------------------------------
   1: [XIO(Current_Metric.6) MOV(Local:4:I.Ch0_NOCMD.GrossWeight,Hardy_HI1769WS_Ch0_Gross_Display_Int) ,XIC(Current_Metric.6) MOV(Local:4:I.Ch0_NOCMD.GrossWeight,Hardy_HI1769WS_Ch0_Gross_Display_Float) ][XIO(Current_Metric.6) MOV(Local:4:I.Ch0_NOCMD.NetWeight,Hardy_HiI1769WS_Ch0_Net_Display_Int) ,XIC(Current_Metric.6) MOV(Local:4:I.Ch0_NOCMD.NetWeight,Hardy_HiI1769WS_Ch0_Net_Display_Float) ];
   // ------------------------------------------------------------------------------------------------------------------------
   // Current Channel Status, Current Command Echo and Current Command Status
   // Channel Status is the overall status of the channel.
   // Current Command Echo is the command that was sent and being echoed back from the module to the PLC.
   // It is often used to confirm a command has been received and the module is communicating back to the PLC.
   // Current Command Status is the status value of the current command being sent.
   // ------------------------------------------------------------------------------------------------------------------------
   2: MOV(Local:4:I.Ch0_NOCMD.ChannelStatus,Hardy_HI1769WS_Ch0_Channel_Status)MOV(Local:4:I.Ch0_NOCMD.CommandEcho,Hardy_HI1769WS_Ch0_Channel_Command_Echo)MOV(Local:4:I.Ch0_NOCMD.CommandStatus,Hardy_HI1769WS_Ch0_Command_Status);
   // ------------------------------------------------------------------------------------------------------------------------
   // Last Command Sent is the last command value that was echoed back and stored in a tag.
   // Last Command status is the status value of the last command echoed back and stored in a tag.
   // ------------------------------------------------------------------------------------------------------------------------
   3: MOV(Status_Return.Cmd,Hardy_HI1769WS_Ch0_Channel_Last_Command)MOV(Status_Return.CmdStatus,Hardy_HI1769WS_Ch0_Last_Command_Status);
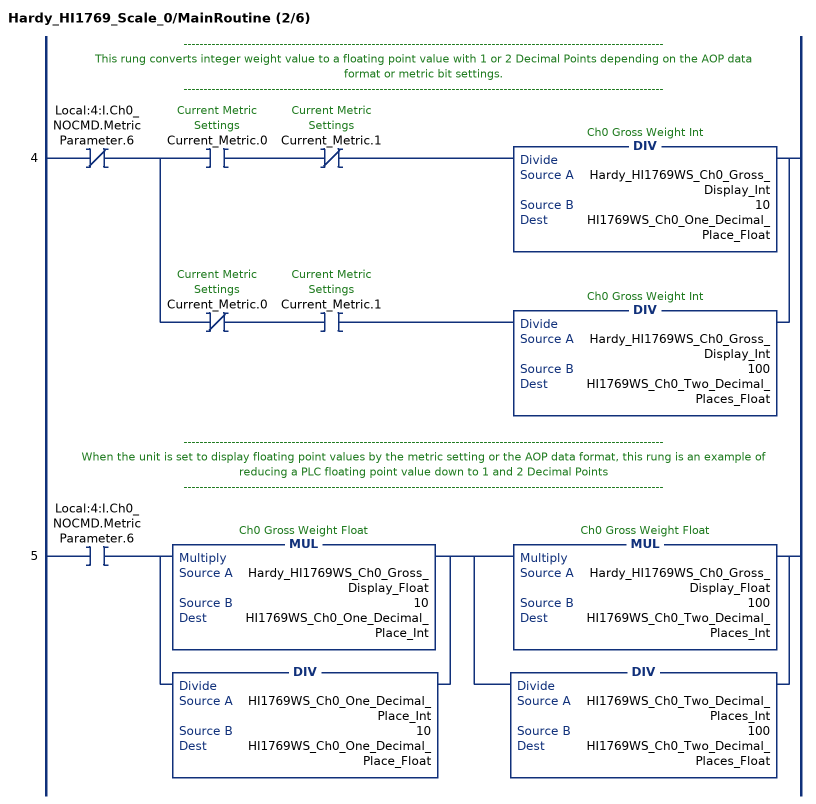
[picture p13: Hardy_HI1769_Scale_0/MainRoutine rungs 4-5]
   // ------------------------------------------------------------------------------------------------------------------------
   // This rung converts integer weight value to a floating point value with 1 or 2 Decimal Points depending on the AOP data format or metric bit settings.
   // ------------------------------------------------------------------------------------------------------------------------
   4: XIO(Local:4:I.Ch0_NOCMD.MetricParameter.6)[XIC(Current_Metric.0) XIO(Current_Metric.1) DIV(Hardy_HI1769WS_Ch0_Gross_Display_Int,10,HI1769WS_Ch0_One_Decimal_Place_Float) ,XIO(Current_Metric.0) XIC(Current_Metric.1) DIV(Hardy_HI1769WS_Ch0_Gross_Display_Int,100,HI1769WS_Ch0_Two_Decimal_Places_Float) ];
   // ------------------------------------------------------------------------------------------------------------------------
   // When the unit is set to display floating point values by the metric setting or the AOP data format, this rung is an example of reducing a PLC floating point value down to 1 and 2 Decimal Points
   // ------------------------------------------------------------------------------------------------------------------------
   5: XIC(Local:4:I.Ch0_NOCMD.MetricParameter.6)[MUL(Hardy_HI1769WS_Ch0_Gross_Display_Float,10,HI1769WS_Ch0_One_Decimal_Place_Int) ,DIV(HI1769WS_Ch0_One_Decimal_Place_Int,10,HI1769WS_Ch0_One_Decimal_Place_Float) ][MUL(Hardy_HI1769WS_Ch0_Gross_Display_Float,100,HI1769WS_Ch0_Two_Decimal_Places_Int) ,DIV(HI1769WS_Ch0_Two_Decimal_Places_Int,100,HI1769WS_Ch0_Two_Decimal_Places_Float) ];
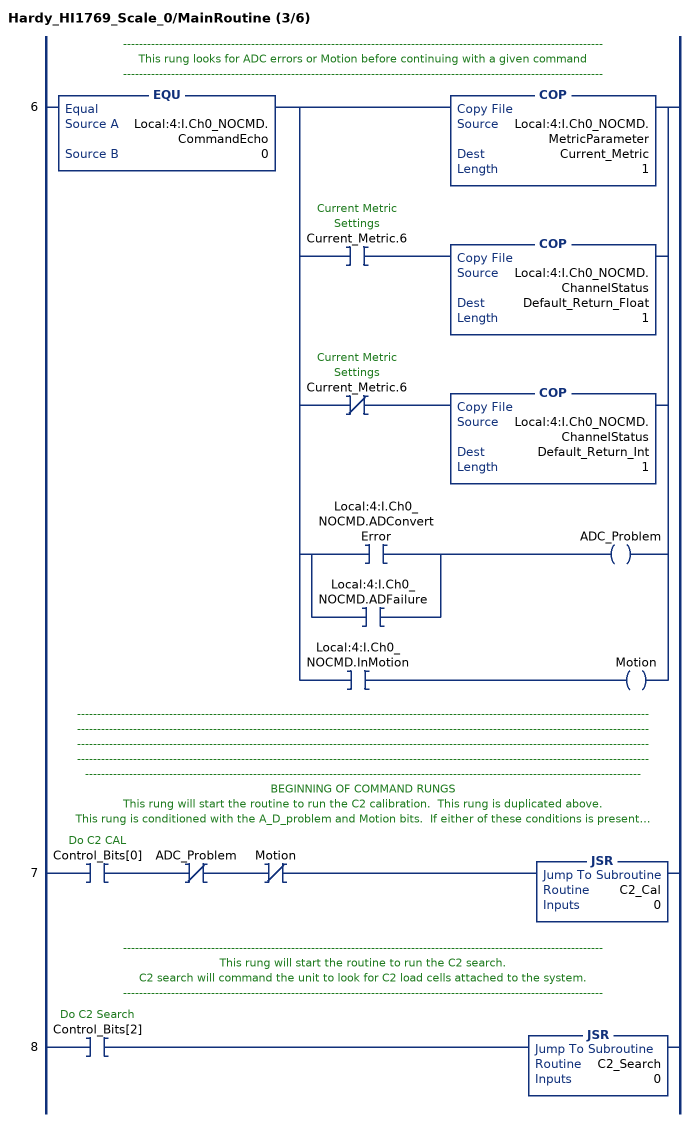
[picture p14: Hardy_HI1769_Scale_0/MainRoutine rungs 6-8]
   // ------------------------------------------------------------------------------------------------------------------------
   // This rung looks for ADC errors or Motion before continuing with a given command
   // ------------------------------------------------------------------------------------------------------------------------
   6: EQU(Local:4:I.Ch0_NOCMD.CommandEcho,0)[COP(Local:4:I.Ch0_NOCMD.MetricParameter,Current_Metric,1) ,XIC(Current_Metric.6) COP(Local:4:I.Ch0_NOCMD.ChannelStatus,Default_Return_Float,1) ,XIO(Current_Metric.6) COP(Local:4:I.Ch0_NOCMD.ChannelStatus,Default_Return_Int,1) ,[XIC(Local:4:I.Ch0_NOCMD.ADConvertError) ,XIC(Local:4:I.Ch0_NOCMD.ADFailure) ] OTE(ADC_Problem) ,XIC(Local:4:I.Ch0_NOCMD.InMotion) OTE(Motion) ];
   // ---------------------------------------------------------------------------------------------------------------------------------------------------------------------------------------------------------------------------------------------------------------------------------------------------------------------------------------------------------------------------------------------------------------------------------------------------------------------------------------------------------------------------------------------------------------------------------------------------------------------------------------------------------------------------------------------------------------------------------------
   // BEGINNING OF COMMAND RUNGS
   // This rung will start the routine to run the C2 calibration.  This rung is duplicated above.
   // This rung is conditioned with the A_D_problem and Motion bits.  If either of these conditions is present, the command would fail, so this will prevent the command from running if failure condition is present.
   // ------------------------------------------------------------------------------------------------------------------------
   7: XIC(Control_Bits[0])XIO(ADC_Problem)XIO(Motion)JSR(C2_Cal,0);
   // ------------------------------------------------------------------------------------------------------------------------
   // This rung will start the routine to run the C2 search.
   // C2 search will command the unit to look for C2 load cells attached to the system.
   // ------------------------------------------------------------------------------------------------------------------------
   8: XIC(Control_Bits[2])JSR(C2_Search,0);
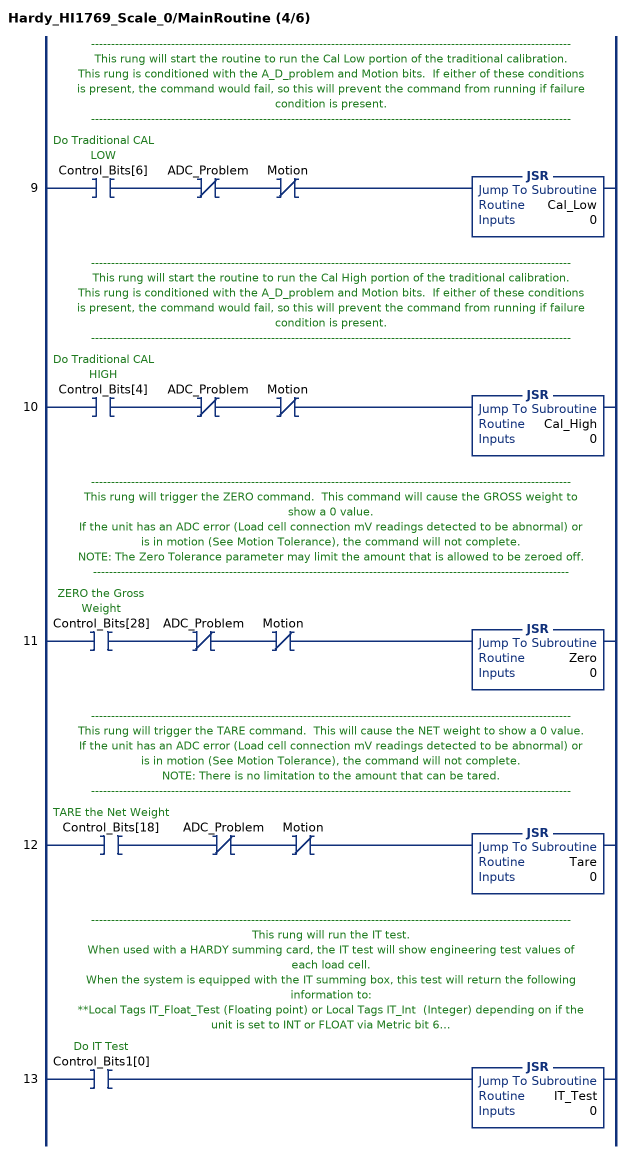
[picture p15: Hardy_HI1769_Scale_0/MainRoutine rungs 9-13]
   // ------------------------------------------------------------------------------------------------------------------------
   // This rung will start the routine to run the Cal Low portion of the traditional calibration.
   // This rung is conditioned with the A_D_problem and Motion bits.  If either of these conditions is present, the command would fail, so this will prevent the command from running if failure condition is present.
   // ------------------------------------------------------------------------------------------------------------------------
   9: XIC(Control_Bits[6])XIO(ADC_Problem)XIO(Motion)JSR(Cal_Low,0);
   // ------------------------------------------------------------------------------------------------------------------------
   // This rung will start the routine to run the Cal High portion of the traditional calibration.
   // This rung is conditioned with the A_D_problem and Motion bits.  If either of these conditions is present, the command would fail, so this will prevent the command from running if failure condition is present.
   // ------------------------------------------------------------------------------------------------------------------------
   10: XIC(Control_Bits[4])XIO(ADC_Problem)XIO(Motion)JSR(Cal_High,0);
   // ------------------------------------------------------------------------------------------------------------------------
   // This rung will trigger the ZERO command.  This command will cause the GROSS weight to show a 0 value.
   // If the unit has an ADC error (Load cell connection mV readings detected to be abnormal) or is in motion (See Motion Tolerance), the command will not complete.
   // NOTE: The Zero Tolerance parameter may limit the amount that is allowed to be zeroed off.
   // -----------------------------------------------------------------------------------------------------------------------
   11: XIC(Control_Bits[28])XIO(ADC_Problem)XIO(Motion)JSR(Zero,0);
   // ------------------------------------------------------------------------------------------------------------------------
   // This rung will trigger the TARE command.  This will cause the NET weight to show a 0 value.
   // If the unit has an ADC error (Load cell connection mV readings detected to be abnormal) or is in motion (See Motion Tolerance), the command will not complete.
   // NOTE: There is no limitation to the amount that can be tared.
   // ------------------------------------------------------------------------------------------------------------------------
   12: XIC(Control_Bits[18])XIO(ADC_Problem)XIO(Motion)JSR(Tare,0);
   // ------------------------------------------------------------------------------------------------------------------------
   // This rung will run the IT test.
   // When used with a HARDY summing card, the IT test will show engineering test values of each load cell.
   // When the system is equipped with the IT summing box, this test will return the following information to:
   // **Local Tags IT_Float_Test (Floating point) or Local Tags IT_Int  (Integer) depending on if the unit is set to INT or FLOAT via Metric bit 6.
   // The IT test may take up to 30 seconds and weight readings may fluctuate.
   // ------------------------------------------------------------------------------------------------------------------------
   13: XIC(Control_Bits1[0])JSR(IT_Test,0);
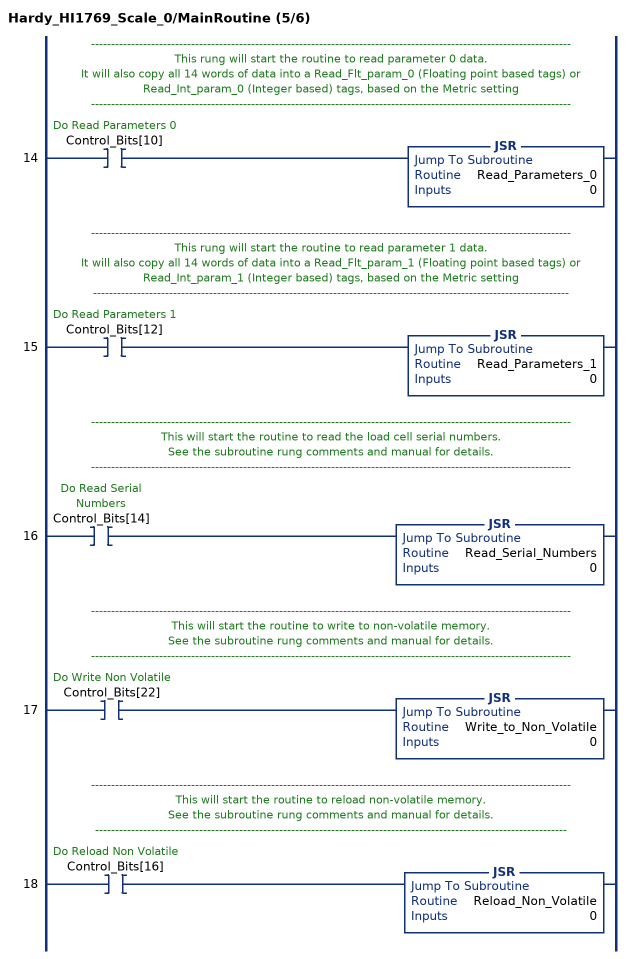
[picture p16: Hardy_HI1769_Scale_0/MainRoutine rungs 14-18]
   // ------------------------------------------------------------------------------------------------------------------------
   // This rung will start the routine to read parameter 0 data.
   // It will also copy all 14 words of data into a Read_Flt_param_0 (Floating point based tags) or Read_Int_param_0 (Integer based) tags, based on the Metric setting
   // ------------------------------------------------------------------------------------------------------------------------
   14: XIC(Control_Bits[10])JSR(Read_Parameters_0,0);
   // ------------------------------------------------------------------------------------------------------------------------
   // This rung will start the routine to read parameter 1 data.
   // It will also copy all 14 words of data into a Read_Flt_param_1 (Floating point based tags) or Read_Int_param_1 (Integer based) tags, based on the Metric setting
   // -----------------------------------------------------------------------------------------------------------------------
   15: XIC(Control_Bits[12])JSR(Read_Parameters_1,0);
   // ------------------------------------------------------------------------------------------------------------------------
   // This will start the routine to read the load cell serial numbers.
   // See the subroutine rung comments and manual for details.
   // ------------------------------------------------------------------------------------------------------------------------
   16: XIC(Control_Bits[14])JSR(Read_Serial_Numbers,0);
   // ------------------------------------------------------------------------------------------------------------------------
   // This will start the routine to write to non-volatile memory.
   // See the subroutine rung comments and manual for details.
   // ------------------------------------------------------------------------------------------------------------------------
   17: XIC(Control_Bits[22])JSR(Write_to_Non_Volatile,0);
   // ------------------------------------------------------------------------------------------------------------------------
   // This will start the routine to reload non-volatile memory.
   // See the subroutine rung comments and manual for details.
   // ----------------------------------------------------------------------------------------------------------------------
   18: XIC(Control_Bits[16])JSR(Reload_Non_Volatile,0);
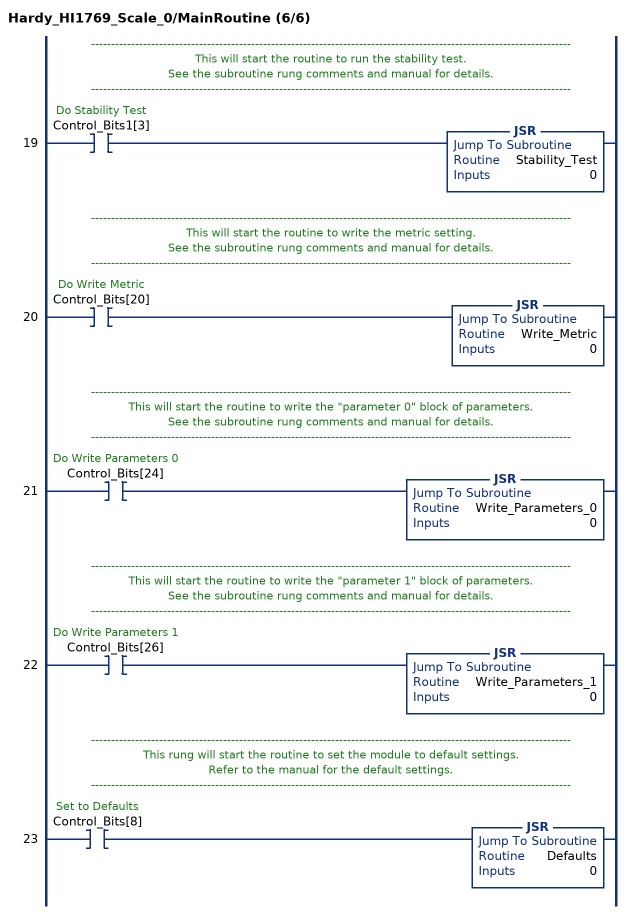
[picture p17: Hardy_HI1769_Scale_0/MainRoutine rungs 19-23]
   // ------------------------------------------------------------------------------------------------------------------------
   // This will start the routine to run the stability test.
   // See the subroutine rung comments and manual for details.
   // ------------------------------------------------------------------------------------------------------------------------
   19: XIC(Control_Bits1[3])JSR(Stability_Test,0);
   // ------------------------------------------------------------------------------------------------------------------------
   // This will start the routine to write the metric setting.
   // See the subroutine rung comments and manual for details.
   // ------------------------------------------------------------------------------------------------------------------------
   20: XIC(Control_Bits[20])JSR(Write_Metric,0);
   // ------------------------------------------------------------------------------------------------------------------------
   // This will start the routine to write the "parameter 0" block of parameters.
   // See the subroutine rung comments and manual for details.
   // ------------------------------------------------------------------------------------------------------------------------
   21: XIC(Control_Bits[24])JSR(Write_Parameters_0,0);
   // ------------------------------------------------------------------------------------------------------------------------
   // This will start the routine to write the "parameter 1" block of parameters.
   // See the subroutine rung comments and manual for details.
   // ------------------------------------------------------------------------------------------------------------------------
   22: XIC(Control_Bits[26])JSR(Write_Parameters_1,0);
   // ------------------------------------------------------------------------------------------------------------------------
   // This rung will start the routine to set the module to default settings.
   // Refer to the manual for the default settings.
   // ------------------------------------------------------------------------------------------------------------------------
   23: XIC(Control_Bits[8])JSR(Defaults,0);
END_ROUTINE
